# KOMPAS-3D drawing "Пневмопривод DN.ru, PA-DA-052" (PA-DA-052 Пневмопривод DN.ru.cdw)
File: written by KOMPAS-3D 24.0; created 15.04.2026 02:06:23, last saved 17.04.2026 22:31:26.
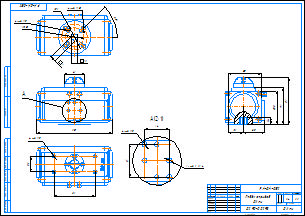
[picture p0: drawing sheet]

Document properties: Автор: DN.ru; Форматы листов документа: A2; Полное имя файла: PA-DA-052 Пневмопривод DN.ru.m3d; Масса: 1.4; Наименование: Пневмопривод DN.ru; Количество листов документа: 1; Примечание: D290-00293

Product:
- Part/product: Пневмопривод DN.ru  | designation PA-DA-052
    Масса: 1.4
    Раздел спецификации: Прочие изделия
    Примечание: D290-00293

Views: Вид 1, Вид:1, Проекционный вид 2, Выносной элемент 6, Выносной элемент А, Выносной элемент
Referenced files in C:\Работа\PA-DA-х Пневмопривод DN.ru\052\: PA-DA-052 Пневмопривод DN.ru.m3d
Referenced files in C:\Program Files\ASCON\KOMPAS-3D v24\Templates\: Чертеж_DN.ru.cdt
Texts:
  objid
  viewid
  PA-DA-052
  Чертеж_DN.ru.cdt
  Пневмопривод
  Пневмопривод DN.ru
  PA-DA-052  Пневмопривод DN.ru
Dimensions and other numbers on the sheet: 0; 3; 2; 4; 40; 608; 147; 4 отв.; 6; 11; 50; 36; 5; 7; 1; 2 отв.; 24; 32; 1:1; 1,4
